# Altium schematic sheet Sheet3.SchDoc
size A4
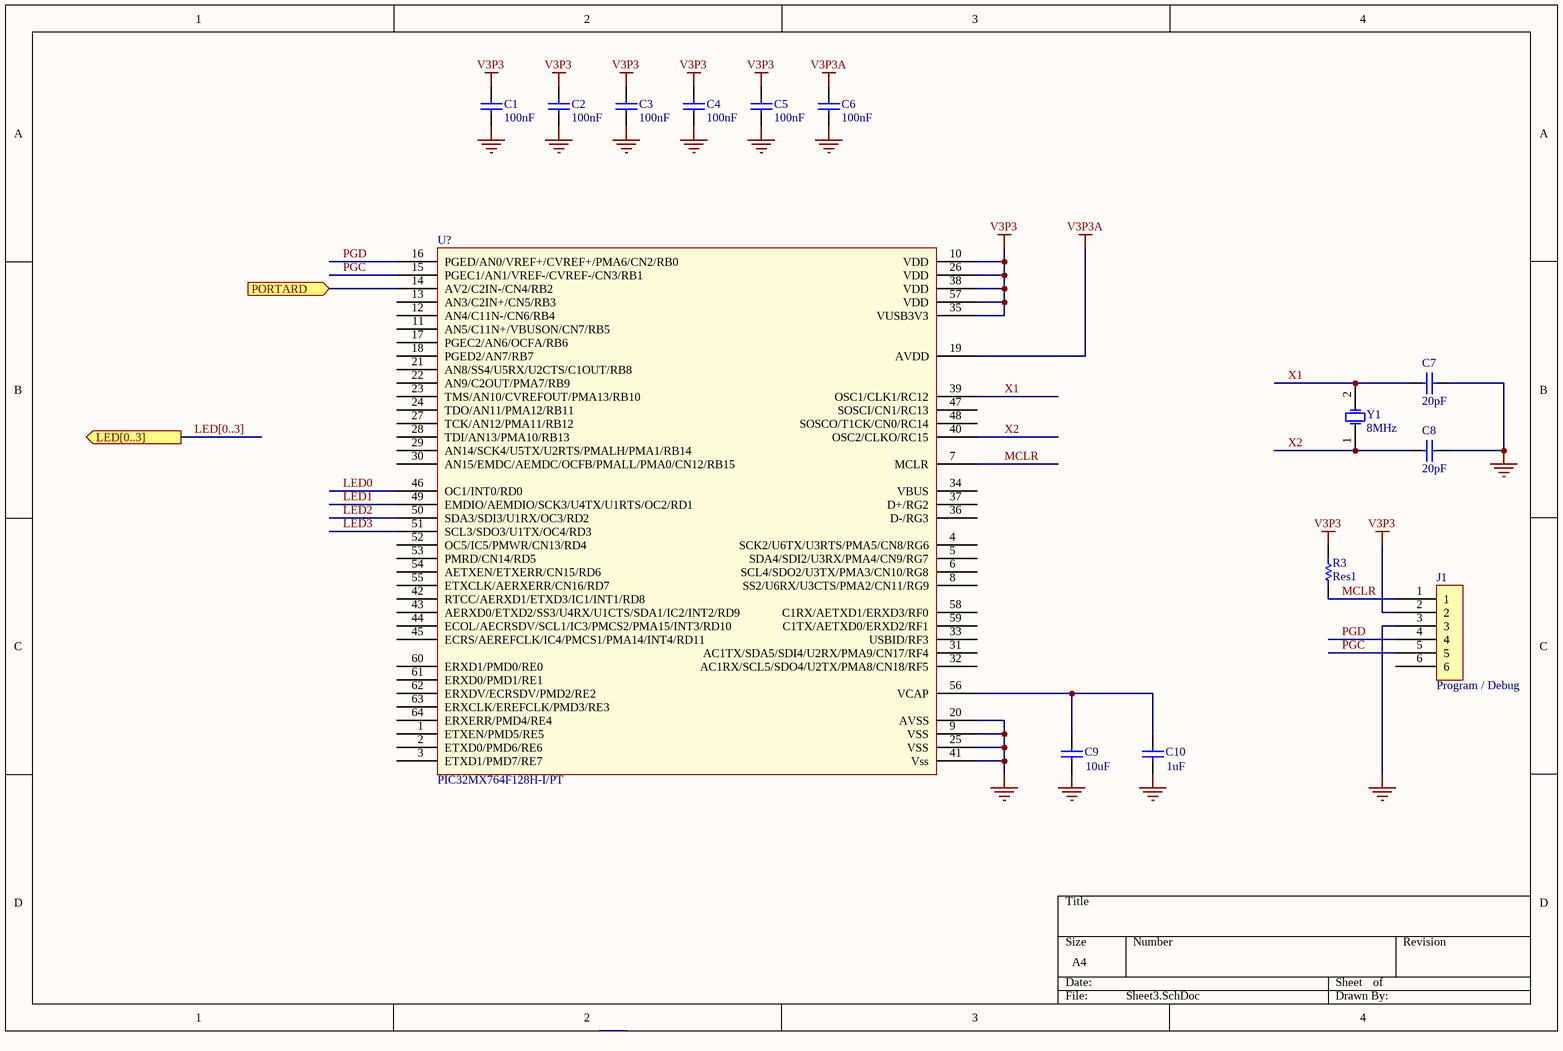
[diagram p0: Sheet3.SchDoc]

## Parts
C1  100nF  [RAD-0.3]
C2  100nF  [RAD-0.3]
C3  100nF  [RAD-0.3]
C4  100nF  [RAD-0.3]
C5  100nF  [RAD-0.3]
C6  100nF  [RAD-0.3]
C7  20pF  [RAD-0.3]
C8  20pF  [RAD-0.3]
C9  10uF  [RAD-0.3]
C10  1uF  [RAD-0.3]
J1  Program / Debug
R3  Res1  [AXIAL-0.3]
U?  PIC32MX764F128H-I/PT
Y1  8MHz  [R38]

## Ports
LED[0..3] (out), PORTARD (in)

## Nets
GND: C1.1 C2.1 C3.1 C4.1 C5.1 C6.1 C7.2 C8.2 C9.1 C10.1 J1.3 U?.9(VSS) U?.20(AVSS) U?.25(VSS) U?.41(Vss)
V3P3: C1.2 C2.2 C3.2 C4.2 C5.2 J1.2 R3.2 U?.10(VDD) U?.26(VDD) U?.35(VUSB3V3) U?.38(VDD) U?.57(VDD)
V3P3A: C6.2 U?.19(AVDD)
LED0: U?.46(OC1/INT0/RD0)
LED1: U?.49(EMDIO/AEMDIO/SCK3/U4TX/U1RTS/OC2/RD1)
LED2: U?.50(SDA3/SDI3/U1RX/OC3/RD2)
LED3: U?.51(SCL3/SDO3/U1TX/OC4/RD3)
MCLR: J1.1 R3.1 U?.7(MCLR)
PGC: J1.5 U?.15(PGEC1/AN1/VREF-/CVREF-/CN3/RB1)
PGD: J1.4 U?.16(PGED/AN0/VREF+/CVREF+/PMA6/CN2/RB0)
PORTARD: U?.14(AV2/C2IN-/CN4/RB2) ; port PORTARD
X1: C7.1 U?.39(OSC1/CLK1/RC12) Y1.2(OSC2)
X2: C8.1 U?.40(OSC2/CLKO/RC15) Y1.1(OSC1)
NetC9_2: C9.2 C10.2 U?.56(VCAP)

Not connected (* = marked no-connect by the designer): J1 6; U? 1(ETXEN/PMD5/RE5) 2(ETXD0/PMD6/RE6) 3(ETXD1/PMD7/RE7) 4(SCK2/U6TX/U3RTS/PMA5/CN8/RG6) 5(SDA4/SDI2/U3RX/PMA4/CN9/RG7) 6(SCL4/SDO2/U3TX/PMA3/CN10/RG8) 8(SS2/U6RX/U3CTS/PMA2/CN11/RG9) 11(AN5/C11N+/VBUSON/CN7/RB5) 12(AN4/C11N-/CN6/RB4) 13(AN3/C2IN+/CN5/RB3) 17(PGEC2/AN6/OCFA/RB6) 18(PGED2/AN7/RB7) 21(AN8/SS4/U5RX/U2CTS/C1OUT/RB8) 22(AN9/C2OUT/PMA7/RB9) 23(TMS/AN10/CVREFOUT/PMA13/RB10) 24(TDO/AN11/PMA12/RB11) 27(TCK/AN12/PMA11/RB12) 28(TDI/AN13/PMA10/RB13) 29(AN14/SCK4/U5TX/U2RTS/PMALH/PMA1/RB14) 30(AN15/EMDC/AEMDC/OCFB/PMALL/PMA0/CN12/RB15) 31(AC1TX/SDA5/SDI4/U2RX/PMA9/CN17/RF4) 32(AC1RX/SCL5/SDO4/U2TX/PMA8/CN18/RF5) 33(USBID/RF3) 34(VBUS) 36(D-/RG3) 37(D+/RG2) 42(RTCC/AERXD1/ETXD3/IC1/INT1/RD8) 43(AERXD0/ETXD2/SS3/U4RX/U1CTS/SDA1/IC2/INT2/RD9) 44(ECOL/AECRSDV/SCL1/IC3/PMCS2/PMA15/INT3/RD10) 45(ECRS/AEREFCLK/IC4/PMCS1/PMA14/INT4/RD11) 47(SOSCI/CN1/RC13) 48(SOSCO/T1CK/CN0/RC14) 52(OC5/IC5/PMWR/CN13/RD4) 53(PMRD/CN14/RD5) 54(AETXEN/ETXERR/CN15/RD6) 55(ETXCLK/AERXERR/CN16/RD7) 58(C1RX/AETXD1/ERXD3/RF0) 59(C1TX/AETXD0/ERXD2/RF1) 60(ERXD1/PMD0/RE0) 61(ERXD0/PMD1/RE1) 62(ERXDV/ECRSDV/PMD2/RE2) 63(ERXCLK/EREFCLK/PMD3/RE3) 64(ERXERR/PMD4/RE4)

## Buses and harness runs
bus LED[0..3] = port LED[0..3]

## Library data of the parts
C1-C8 = Cap: Capacitor; Fournisseur: .; Precision: 50V X5R
C9 = Cap: Capacitor; Fournisseur: Farnell; Ref. Fournisseur: 2309029; Fabricant: TDK; Ref. Fabricant: C2012X5ROJ106M/1.25; Precision: 6.3V X5R
C10 = Cap: Capacitor; Fournisseur: Farnell; Ref. Fournisseur: .
J1 = Program / Debug: Fournisseur: Farnell; Fabricant: Molex; Ref.Fournisseur: 1125368; Ref.Fabricant: 53398-0671
R3 = Res1: Resistor; Valeur: 4.7k; Precision: 1%
U? = PIC32MX764F128H-I/PT: Fabricant: Microchip; Fournisseur: Farnell; RefFournisseur: 1971889
Y1 = XTAL: Crystal Oscillator; Fabricant: FOX ELECTRONICS; Ref.Fabricant: FOXSDLF/080-20; Ref.Fournisseur: 2063972; Fournisseur: Farnell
